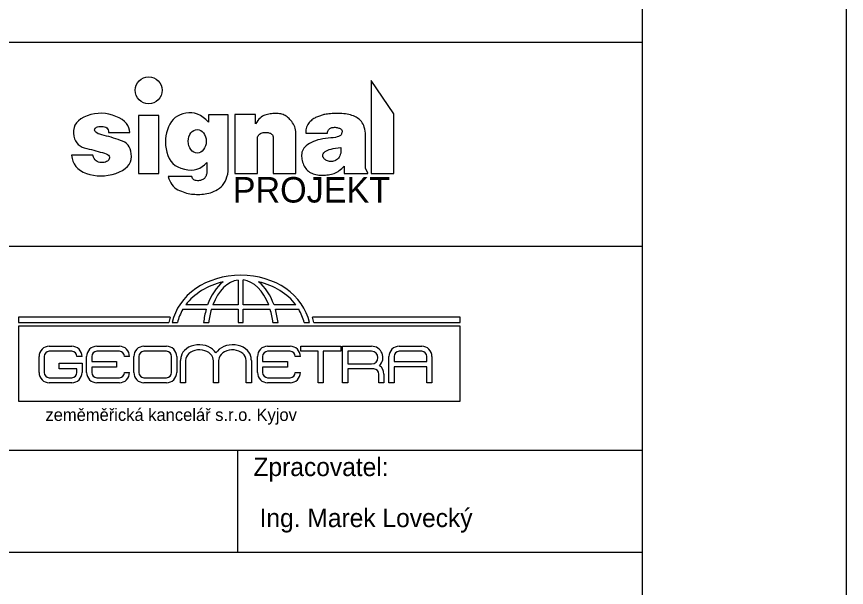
# Model space of a CAD drawing. Extents: x 1391 to 5528, y -6194 to 565.
# Drawn here: x 4054.2 to 4135.6, y -5727.5 to -5671.5 of the extents above; entities that cross this region are included whole.
import ezdxf

# ---------------------------------------------------------------- set-up
doc = ezdxf.new("R2010")
doc.units = 0
for name, color, linetype in [('Default', 7, 'Continuous'), ('Vrstva 1', 7, 'Continuous'), ('Vrstva 11', 7, 'Continuous'), ('Vrstva 17', 7, 'Continuous'), ('Vrstva 6', 7, 'Continuous')]:
    doc.layers.add(name, color=color, linetype=linetype)

msp = doc.modelspace()

# ---------------------------------------------------------------- linework, layer by layer
at = {"layer": 'Default'}
msp.add_lwpolyline([(3925.563, -5826.032), (4135.563, -5826.032), (4135.563, -5529.032), (3925.563, -5529.032)], close=True, dxfattribs=at)
at = {"layer": 'Vrstva 1'}
msp.add_lwpolyline([(3945.563, -5549.032), (4115.563, -5549.032), (4115.563, -5809.032), (3945.563, -5809.032)], close=True, dxfattribs=at)
at = {"layer": 'Vrstva 11'}
for points in [[(4091.228, -5686.911), (4091.228, -5681.071), (4088.988, -5677.791), (4088.988, -5686.911), (4091.228, -5686.911)], [(4062.499, -5687.146), (4062.861, -5687.13), (4063.228, -5687.082), (4063.599, -5687.003), (4063.975, -5686.893), (4064.329, -5686.756), (4064.637, -5686.6), (4064.898, -5686.424), (4065.112, -5686.228), (4065.28, -5686.012), (4065.4, -5685.776), (4065.474, -5685.521), (4065.5, -5685.245), (4065.49, -5684.971), (4065.451, -5684.722), (4065.385, -5684.498), (4065.291, -5684.299), (4065.17, -5684.124), (4065.021, -5683.974), (4064.844, -5683.849), (4064.639, -5683.748), (4064.42, -5683.662), (4064.198, -5683.58), (4063.973, -5683.503), (4063.747, -5683.43), (4063.518, -5683.361), (4063.287, -5683.297), (4063.054, -5683.237), (4062.818, -5683.182), (4062.596, -5683.127), (4062.405, -5683.068), (4062.244, -5683.005), (4062.114, -5682.938), (4062.014, -5682.867), (4061.945, -5682.791), (4061.906, -5682.712), (4061.897, -5682.629), (4061.914, -5682.55), (4061.95, -5682.481), (4062.006, -5682.423), (4062.082, -5682.376), (4062.178, -5682.339), (4062.294, -5682.314), (4062.429, -5682.299), (4062.585, -5682.296), (4062.74, -5682.306), (4062.875, -5682.335), (4062.99, -5682.383), (4063.085, -5682.448), (4063.16, -5682.532), (4063.214, -5682.635), (4063.249, -5682.755), (4063.263, -5682.894), (4065.342, -5682.894), (4065.323, -5682.652), (4065.261, -5682.422), (4065.156, -5682.205), (4065.008, -5682.001), (4064.817, -5681.809), (4064.583, -5681.631), (4064.307, -5681.464), (4063.987, -5681.311), (4063.645, -5681.182), (4063.3, -5681.087), (4062.952, -5681.027), (4062.602, -5681.002), (4062.249, -5681.012), (4061.894, -5681.057), (4061.535, -5681.137), (4061.174, -5681.252), (4060.836, -5681.394), (4060.547, -5681.557), (4060.306, -5681.74), (4060.114, -5681.944), (4059.971, -5682.168), (4059.876, -5682.413), (4059.83, -5682.679), (4059.832, -5682.964), (4059.872, -5683.246), (4059.938, -5683.498), (4060.03, -5683.72), (4060.148, -5683.913), (4060.293, -5684.076), (4060.464, -5684.21), (4060.661, -5684.315), (4060.885, -5684.389), (4061.12, -5684.449), (4061.351, -5684.509), (4061.578, -5684.568), (4061.802, -5684.627), (4062.023, -5684.686), (4062.239, -5684.744), (4062.452, -5684.802), (4062.662, -5684.86), (4062.854, -5684.92), (4063.016, -5684.984), (4063.146, -5685.053), (4063.246, -5685.126), (4063.314, -5685.204), (4063.352, -5685.287), (4063.359, -5685.374), (4063.335, -5685.465), (4063.289, -5685.553), (4063.228, -5685.629), (4063.152, -5685.694), (4063.062, -5685.747), (4062.958, -5685.789), (4062.84, -5685.819), (4062.707, -5685.837), (4062.559, -5685.844), (4062.411, -5685.833), (4062.275, -5685.8), (4062.152, -5685.744), (4062.04, -5685.666), (4061.942, -5685.565), (4061.855, -5685.441), (4061.781, -5685.294), (4061.72, -5685.126), (4059.639, -5685.126), (4059.683, -5685.433), (4059.767, -5685.715), (4059.89, -5685.973), (4060.052, -5686.206), (4060.254, -5686.416), (4060.496, -5686.601), (4060.778, -5686.762), (4061.099, -5686.899), (4061.442, -5687.008), (4061.79, -5687.085), (4062.142, -5687.131), (4062.499, -5687.146)], [(4068.188, -5686.911), (4068.188, -5681.231), (4066.188, -5681.231), (4066.188, -5686.911), (4068.188, -5686.911)], [(4072.047, -5688.954), (4072.216, -5688.95), (4072.386, -5688.941), (4072.558, -5688.928), (4072.731, -5688.91), (4072.905, -5688.883), (4073.079, -5688.844), (4073.253, -5688.793), (4073.426, -5688.729), (4073.6, -5688.654), (4073.772, -5688.566), (4073.945, -5688.466), (4074.117, -5688.354), (4074.282, -5688.225), (4074.43, -5688.072), (4074.563, -5687.896), (4074.679, -5687.698), (4074.78, -5687.476), (4074.865, -5687.231), (4074.934, -5686.963), (4074.988, -5686.671), (4074.988, -5681.151), (4073.068, -5681.151), (4073.068, -5681.871), (4072.802, -5681.617), (4072.531, -5681.404), (4072.257, -5681.232), (4071.978, -5681.101), (4071.695, -5681.011), (4071.407, -5680.962), (4071.116, -5680.954), (4070.82, -5680.988), (4070.533, -5681.056), (4070.267, -5681.153), (4070.024, -5681.278), (4069.802, -5681.432), (4069.602, -5681.614), (4069.423, -5681.825), (4069.267, -5682.065), (4069.132, -5682.333), (4069.022, -5682.618), (4068.937, -5682.911), (4068.878, -5683.212), (4068.845, -5683.519), (4068.838, -5683.834), (4068.857, -5684.155), (4068.901, -5684.484), (4068.972, -5684.82), (4069.072, -5685.144), (4069.205, -5685.434), (4069.37, -5685.692), (4069.568, -5685.918), (4069.799, -5686.11), (4070.062, -5686.27), (4070.358, -5686.398), (4070.687, -5686.493), (4071.023, -5686.551), (4071.342, -5686.568), (4071.643, -5686.545), (4071.926, -5686.481), (4072.191, -5686.376), (4072.438, -5686.23), (4072.668, -5686.044), (4072.88, -5685.817), (4072.88, -5686.894), (4072.861, -5686.982), (4072.838, -5687.063), (4072.81, -5687.139), (4072.778, -5687.209), (4072.742, -5687.274), (4072.701, -5687.333), (4072.655, -5687.386), (4072.605, -5687.433), (4072.55, -5687.474), (4072.487, -5687.511), (4072.417, -5687.542), (4072.34, -5687.567), (4072.256, -5687.587), (4072.165, -5687.602), (4072.067, -5687.612), (4071.962, -5687.616), (4071.858, -5687.61), (4071.765, -5687.592), (4071.682, -5687.56), (4071.609, -5687.515), (4071.546, -5687.456), (4071.493, -5687.385), (4071.451, -5687.3), (4071.418, -5687.202), (4069.111, -5687.202), (4069.18, -5687.429), (4069.264, -5687.638), (4069.361, -5687.828), (4069.472, -5688), (4069.596, -5688.152), (4069.735, -5688.286), (4069.887, -5688.401), (4070.053, -5688.498), (4070.225, -5688.581), (4070.396, -5688.655), (4070.565, -5688.72), (4070.733, -5688.777), (4070.899, -5688.826), (4071.064, -5688.866), (4071.227, -5688.897), (4071.389, -5688.919), (4071.551, -5688.935), (4071.715, -5688.946), (4071.88, -5688.952), (4072.047, -5688.954)], [(4081.628, -5686.911), (4081.628, -5683.111), (4081.624, -5682.942), (4081.61, -5682.778), (4081.586, -5682.622), (4081.55, -5682.472), (4081.504, -5682.328), (4081.447, -5682.191), (4081.379, -5682.061), (4081.301, -5681.937), (4081.216, -5681.821), (4081.129, -5681.713), (4081.04, -5681.613), (4080.949, -5681.521), (4080.856, -5681.438), (4080.761, -5681.363), (4080.664, -5681.296), (4080.565, -5681.237), (4080.462, -5681.185), (4080.356, -5681.141), (4080.245, -5681.104), (4080.13, -5681.073), (4080.011, -5681.05), (4079.887, -5681.033), (4079.759, -5681.023), (4079.627, -5681.021), (4079.493, -5681.024), (4079.361, -5681.032), (4079.229, -5681.045), (4079.099, -5681.063), (4078.97, -5681.086), (4078.842, -5681.114), (4078.716, -5681.147), (4078.59, -5681.184), (4078.467, -5681.233), (4078.345, -5681.297), (4078.226, -5681.379), (4078.11, -5681.476), (4077.996, -5681.59), (4077.884, -5681.721), (4077.775, -5681.868), (4077.668, -5682.031), (4077.668, -5681.111), (4075.628, -5681.111), (4075.628, -5686.911), (4077.868, -5686.911), (4077.868, -5683.351), (4077.902, -5683.26), (4077.946, -5683.179), (4078.001, -5683.108), (4078.065, -5683.047), (4078.139, -5682.996), (4078.223, -5682.955), (4078.317, -5682.924), (4078.421, -5682.903), (4078.527, -5682.89), (4078.628, -5682.883), (4078.723, -5682.883), (4078.814, -5682.888), (4078.899, -5682.899), (4078.978, -5682.917), (4079.053, -5682.941), (4079.122, -5682.97), (4079.184, -5683.005), (4079.238, -5683.044), (4079.284, -5683.086), (4079.321, -5683.131), (4079.35, -5683.181), (4079.371, -5683.234), (4079.383, -5683.291), (4079.388, -5683.351), (4079.388, -5686.911), (4081.628, -5686.911)], [(4084.19, -5687.075), (4084.352, -5687.073), (4084.51, -5687.064), (4084.663, -5687.05), (4084.812, -5687.03), (4084.956, -5687.004), (4085.097, -5686.972), (4085.233, -5686.935), (4085.364, -5686.892), (4085.493, -5686.841), (4085.62, -5686.779), (4085.746, -5686.707), (4085.869, -5686.625), (4085.991, -5686.532), (4086.112, -5686.429), (4086.23, -5686.315), (4086.348, -5686.191), (4086.348, -5686.911), (4088.668, -5686.911), (4088.668, -5686.831), (4088.428, -5686.431), (4088.428, -5682.951), (4088.401, -5682.747), (4088.365, -5682.557), (4088.32, -5682.381), (4088.265, -5682.22), (4088.201, -5682.073), (4088.127, -5681.941), (4088.043, -5681.823), (4087.95, -5681.719), (4087.849, -5681.627), (4087.742, -5681.541), (4087.628, -5681.462), (4087.508, -5681.39), (4087.382, -5681.325), (4087.25, -5681.267), (4087.111, -5681.216), (4086.966, -5681.172), (4086.814, -5681.134), (4086.655, -5681.102), (4086.489, -5681.075), (4086.315, -5681.055), (4086.135, -5681.04), (4085.947, -5681.03), (4085.751, -5681.027), (4085.549, -5681.029), (4085.35, -5681.035), (4085.166, -5681.043), (4084.997, -5681.054), (4084.843, -5681.066), (4084.703, -5681.081), (4084.578, -5681.098), (4084.467, -5681.118), (4084.372, -5681.14), (4084.283, -5681.163), (4084.194, -5681.189), (4084.104, -5681.217), (4084.013, -5681.246), (4083.921, -5681.278), (4083.829, -5681.311), (4083.737, -5681.346), (4083.643, -5681.384), (4083.55, -5681.425), (4083.458, -5681.474), (4083.366, -5681.529), (4083.276, -5681.592), (4083.187, -5681.661), (4083.099, -5681.736), (4083.012, -5681.819), (4082.926, -5681.909), (4082.845, -5682.006), (4082.776, -5682.113), (4082.718, -5682.229), (4082.67, -5682.355), (4082.633, -5682.49), (4082.607, -5682.634), (4082.592, -5682.788), (4082.588, -5682.951), (4084.708, -5682.951), (4084.723, -5682.855), (4084.747, -5682.768), (4084.78, -5682.69), (4084.821, -5682.621), (4084.872, -5682.561), (4084.93, -5682.511), (4084.998, -5682.469), (4085.073, -5682.437), (4085.154, -5682.413), (4085.235, -5682.395), (4085.317, -5682.384), (4085.399, -5682.379), (4085.481, -5682.381), (4085.565, -5682.389), (4085.648, -5682.404), (4085.732, -5682.425), (4085.813, -5682.45), (4085.884, -5682.478), (4085.947, -5682.508), (4086, -5682.54), (4086.045, -5682.574), (4086.082, -5682.611), (4086.109, -5682.649), (4086.128, -5682.69), (4086.14, -5682.733), (4086.145, -5682.778), (4086.144, -5682.827), (4086.136, -5682.878), (4086.122, -5682.932), (4086.103, -5682.989), (4086.076, -5683.049), (4086.044, -5683.112), (4085.993, -5683.173), (4085.912, -5683.229), (4085.801, -5683.28), (4085.659, -5683.325), (4085.487, -5683.365), (4085.285, -5683.4), (4085.052, -5683.429), (4084.789, -5683.453), (4084.517, -5683.48), (4084.258, -5683.517), (4084.01, -5683.565), (4083.775, -5683.624), (4083.553, -5683.693), (4083.342, -5683.772), (4083.144, -5683.862), (4082.958, -5683.963), (4082.789, -5684.071), (4082.641, -5684.184), (4082.513, -5684.301), (4082.407, -5684.423), (4082.321, -5684.549), (4082.256, -5684.68), (4082.212, -5684.815), (4082.189, -5684.955), (4082.181, -5685.096), (4082.182, -5685.236), (4082.192, -5685.375), (4082.211, -5685.513), (4082.239, -5685.65), (4082.276, -5685.785), (4082.322, -5685.919), (4082.377, -5686.053), (4082.44, -5686.181), (4082.51, -5686.3), (4082.587, -5686.41), (4082.671, -5686.512), (4082.761, -5686.604), (4082.859, -5686.688), (4082.964, -5686.763), (4083.075, -5686.829), (4083.193, -5686.887), (4083.317, -5686.937), (4083.447, -5686.979), (4083.584, -5687.014), (4083.726, -5687.041), (4083.875, -5687.06), (4084.03, -5687.072), (4084.19, -5687.075)], [(4084.906, -5685.731), (4084.803, -5685.71), (4084.708, -5685.682), (4084.622, -5685.646), (4084.543, -5685.603), (4084.472, -5685.551), (4084.409, -5685.492), (4084.354, -5685.426), (4084.307, -5685.351), (4084.273, -5685.273), (4084.255, -5685.196), (4084.254, -5685.12), (4084.27, -5685.045), (4084.302, -5684.971), (4084.351, -5684.898), (4084.417, -5684.826), (4084.5, -5684.754), (4084.603, -5684.686), (4084.732, -5684.623), (4084.886, -5684.565), (4085.065, -5684.513), (4085.269, -5684.465), (4085.498, -5684.424), (4085.753, -5684.387), (4086.032, -5684.356), (4086.037, -5684.554), (4086.028, -5684.736), (4086.006, -5684.902), (4085.972, -5685.052), (4085.924, -5685.186), (4085.864, -5685.303), (4085.79, -5685.404), (4085.704, -5685.49), (4085.611, -5685.561), (4085.515, -5685.62), (4085.418, -5685.668), (4085.319, -5685.704), (4085.219, -5685.728), (4085.116, -5685.741), (4085.012, -5685.742), (4084.906, -5685.731)]]:
    msp.add_lwpolyline(points, dxfattribs=at)
msp.add_circle((4067.188, -5678.751), 1.32, dxfattribs=at)
msp.add_ellipse((4071.948, -5683.751), major_axis=(0, 1.16), ratio=0.758621, dxfattribs=at)
at = {"layer": 'Vrstva 17'}
for p, q in [((4075.958, -5697.345), (4075.958, -5699.791)), ((4076.465, -5699.791), (4076.465, -5697.343)), ((4072.965, -5699.791), (4070.82, -5699.791)), ((4075.958, -5699.791), (4073.482, -5699.791)), ((4078.96, -5699.791), (4076.465, -5699.791)), ((4081.622, -5699.791), (4079.477, -5699.791)), ((4070.545, -5700.202), (4072.832, -5700.202)), ((4073.342, -5700.202), (4075.958, -5700.202)), ((4075.958, -5700.202), (4075.958, -5701.523)), ((4076.465, -5701.523), (4076.465, -5700.202)), ((4076.465, -5700.202), (4079.099, -5700.202)), ((4079.609, -5700.202), (4081.897, -5700.202)), ((4069.314, -5700.991), (4054.433, -5700.991)), ((4054.433, -5700.991), (4054.433, -5701.523)), ((4054.433, -5701.523), (4069.176, -5701.523)), ((4069.502, -5701.523), (4070.019, -5701.523)), ((4072.575, -5701.523), (4073.075, -5701.523)), ((4075.958, -5701.523), (4076.465, -5701.523)), ((4079.366, -5701.523), (4079.866, -5701.523)), ((4082.423, -5701.523), (4082.94, -5701.523)), ((4097.712, -5700.991), (4083.233, -5700.991)), ((4083.371, -5701.523), (4097.712, -5701.523)), ((4097.712, -5701.523), (4097.712, -5700.991)), ((4097.71, -5701.867), (4054.427, -5701.867)), ((4054.427, -5701.867), (4054.427, -5709.205)), ((4097.71, -5709.205), (4097.71, -5701.867)), ((4057.452, -5703.833), (4059.663, -5703.833)), ((4062.108, -5703.833), (4064.319, -5703.833)), ((4066.732, -5703.833), (4068.943, -5703.833)), ((4078.851, -5703.833), (4081.061, -5703.833)), ((4086.188, -5703.833), (4089.032, -5703.833)), ((4091.736, -5703.833), (4093.947, -5703.833)), ((4056.454, -5706.417), (4056.454, -5704.831)), ((4056.953, -5704.831), (4056.953, -5706.417)), ((4059.663, -5704.332), (4057.452, -5704.332)), ((4060.66, -5704.831), (4060.162, -5704.831)), ((4061.11, -5706.417), (4061.11, -5704.831)), ((4061.609, -5704.831), (4061.609, -5705.341)), ((4064.319, -5704.332), (4062.108, -5704.332)), ((4065.317, -5704.831), (4064.818, -5704.831)), ((4065.734, -5706.417), (4065.734, -5704.831)), ((4066.233, -5704.831), (4066.233, -5706.417)), ((4068.943, -5704.332), (4066.732, -5704.332)), ((4069.442, -5706.417), (4069.442, -5704.831)), ((4069.941, -5704.831), (4069.941, -5706.417)), ((4077.853, -5706.417), (4077.853, -5704.831)), ((4078.352, -5704.831), (4078.352, -5705.341)), ((4081.061, -5704.332), (4078.851, -5704.332)), ((4082.059, -5704.831), (4081.56, -5704.831)), ((4083.794, -5707.415), (4083.794, -5704.32)), ((4084.297, -5704.32), (4084.297, -5707.415)), ((4089.032, -5704.322), (4086.692, -5704.322)), ((4086.692, -5704.322), (4086.692, -5705.572)), ((4090.738, -5707.415), (4090.738, -5704.831)), ((4091.237, -5704.831), (4091.237, -5705.339)), ((4093.947, -5704.332), (4091.736, -5704.332)), ((4094.446, -5705.339), (4094.446, -5704.831)), ((4094.945, -5704.831), (4094.945, -5707.415)), ((4058.427, -5706.039), (4058.427, -5705.494)), ((4058.427, -5705.494), (4060.66, -5705.494)), ((4060.66, -5705.494), (4060.66, -5706.417)), ((4061.609, -5705.341), (4064.052, -5705.341)), ((4064.052, -5705.341), (4064.052, -5705.886)), ((4070.313, -5707.415), (4070.313, -5705.23)), ((4070.814, -5705.23), (4070.814, -5707.415)), ((4073.533, -5707.415), (4073.533, -5705.23)), ((4074.033, -5705.23), (4074.033, -5707.415)), ((4076.752, -5707.415), (4076.752, -5705.23)), ((4077.253, -5705.23), (4077.253, -5707.415)), ((4078.352, -5705.341), (4080.795, -5705.341)), ((4080.795, -5705.341), (4080.795, -5705.886)), ((4086.692, -5705.572), (4089.032, -5705.572)), ((4091.237, -5705.339), (4094.446, -5705.339)), ((4060.162, -5706.039), (4058.427, -5706.039)), ((4060.162, -5706.417), (4060.162, -5706.039)), ((4064.052, -5705.886), (4061.609, -5705.886)), ((4061.609, -5705.886), (4061.609, -5706.417)), ((4064.818, -5706.417), (4065.317, -5706.417)), ((4080.795, -5705.886), (4078.352, -5705.886)), ((4078.352, -5705.886), (4078.352, -5706.417)), ((4081.56, -5706.417), (4082.059, -5706.417)), ((4089.032, -5706.06), (4086.692, -5706.06)), ((4089.247, -5706.064), (4089.032, -5706.06)), ((4089.746, -5707.415), (4089.746, -5706.563)), ((4090.244, -5706.563), (4090.244, -5707.415)), ((4094.446, -5705.843), (4091.237, -5705.843)), ((4091.237, -5705.843), (4091.237, -5707.415)), ((4094.446, -5707.415), (4094.446, -5705.843)), ((4057.452, -5706.916), (4059.663, -5706.916)), ((4062.108, -5706.916), (4064.319, -5706.916)), ((4066.732, -5706.916), (4068.943, -5706.916)), ((4078.851, -5706.916), (4081.061, -5706.916)), ((4059.663, -5707.415), (4057.452, -5707.415)), ((4064.319, -5707.415), (4062.108, -5707.415)), ((4068.943, -5707.415), (4066.732, -5707.415)), ((4070.814, -5707.415), (4070.313, -5707.415)), ((4074.033, -5707.415), (4073.533, -5707.415)), ((4077.253, -5707.415), (4076.752, -5707.415)), ((4081.061, -5707.415), (4078.851, -5707.415)), ((4084.297, -5707.415), (4083.794, -5707.415)), ((4090.244, -5707.415), (4089.746, -5707.415)), ((4091.237, -5707.415), (4090.738, -5707.415)), ((4094.945, -5707.415), (4094.446, -5707.415)), ((4054.427, -5709.205), (4097.71, -5709.205))]:
    msp.add_line(p, q, dxfattribs=at)
for points in [[(4083.794, -5704.32), (4082.096, -5704.32), (4082.096, -5703.833), (4086.009, -5703.833)], [(4086.009, -5703.833), (4086.009, -5704.32), (4084.297, -5704.32)], [(4086.692, -5706.06), (4086.692, -5707.415), (4086.188, -5707.415), (4086.188, -5703.833)]]:
    msp.add_lwpolyline(points, dxfattribs=at)
for centre, radius, start, end in [((4057.452, -5704.831), 0.998, 90, 180), ((4059.663, -5704.831), 0.998, 360, 90), ((4062.108, -5704.831), 0.998, 90, 180), ((4064.319, -5704.831), 0.998, 360, 90), ((4066.732, -5704.831), 0.998, 90, 180), ((4068.943, -5704.831), 0.998, 360, 90), ((4078.851, -5704.831), 0.998, 90, 180), ((4081.061, -5704.831), 0.998, 360, 90), ((4089.032, -5704.947), 1.114, 314.45734, 90), ((4091.736, -5704.831), 0.998, 90, 180), ((4093.947, -5704.831), 0.998, 360, 90), ((4057.452, -5704.831), 0.499, 90, 180), ((4059.663, -5704.831), 0.499, 0, 90), ((4062.108, -5704.831), 0.499, 90, 180), ((4064.319, -5704.831), 0.499, 0, 90), ((4066.732, -5704.831), 0.499, 90, 180), ((4068.943, -5704.831), 0.499, 0, 90), ((4072.25, -5705.28), 1.938, 166.96576, 178.52091), ((4072.579, -5705.294), 0.957, 3.86486, 22.41569), ((4075.315, -5705.28), 1.938, 1.47909, 13.03424), ((4078.851, -5704.831), 0.499, 90, 180), ((4081.061, -5704.831), 0.499, 0, 90), ((4089.032, -5704.947), 0.625, 270, 90), ((4091.736, -5704.831), 0.499, 90, 180), ((4093.947, -5704.831), 0.499, 0, 90), ((4075.266, -5705.352), 1.238, 162.61388, 174.3506), ((4089.247, -5706.563), 0.998, 360, 55.44734), ((4057.452, -5706.417), 0.998, 180, 270), ((4057.452, -5706.417), 0.499, 180, 270), ((4059.663, -5706.417), 0.998, 270, 0), ((4059.663, -5706.417), 0.499, 270, 0), ((4062.108, -5706.417), 0.998, 180, 270), ((4062.108, -5706.417), 0.499, 180, 270), ((4064.319, -5706.417), 0.998, 270, 0), ((4064.319, -5706.417), 0.499, 270, 0), ((4066.732, -5706.417), 0.998, 180, 270), ((4066.732, -5706.417), 0.499, 180, 270), ((4068.943, -5706.417), 0.998, 270, 0), ((4068.943, -5706.417), 0.499, 270, 0), ((4078.851, -5706.417), 0.998, 180, 270), ((4078.851, -5706.417), 0.499, 180, 270), ((4081.061, -5706.417), 0.998, 270, 0), ((4081.061, -5706.417), 0.499, 270, 0), ((4089.247, -5706.563), 0.499, 0, 90)]:
    msp.add_arc(centre, radius, start, end, dxfattribs=at)
for centre, major_axis, ratio, start_param, end_param in [((4076.221, -5702.395), (-6.804, 0), 0.811768, 3.300239, 6.124539), ((4076.221, -5702.395), (-6.296, 0), 0.804826, 4.992897, 5.743383), ((4076.221, -5702.395), (0, 5.524), 0.668443, 0.491666, 1.079789), ((4076.221, -5702.395), (0, 5.067), 0.630136, 0.08224, 1.030995), ((4076.221, -5702.395), (0, 5.067), 0.630136, 5.252191, 6.206521), ((4076.221, -5702.395), (0, 5.524), 0.668443, 5.203397, 5.79152), ((4076.221, -5702.395), (-6.296, 0), 0.804826, 3.681394, 4.431881), ((4076.221, -5702.395), (-6.296, 0), 0.804826, 5.835664, 6.110118), ((4076.221, -5702.395), (0, 5.524), 0.668443, 1.16256, 1.41215), ((4076.221, -5702.395), (0, 5.067), 0.630136, 1.123275, 1.397729), ((4076.221, -5702.395), (0, 5.067), 0.630136, 4.885456, 5.159911), ((4076.221, -5702.395), (0, 5.524), 0.668443, 4.871035, 5.120625), ((4076.221, -5702.395), (-6.296, 0), 0.804826, 3.31466, 3.589114), ((4075.895, -5702.395), (-6.804, 0), 0.811768, 6.026233, 6.124539), ((4076.653, -5702.395), (-6.804, 0), 0.811768, 3.300239, 3.398545), ((4072.142, -5705.074), (1.805, 0), 0.766187, 0.429647, 2.97338), ((4075.424, -5705.074), (-1.805, 0), 0.766187, 3.309805, 5.853538), ((4072.167, -5705.23), (1.354, 0), 0.766187, 0.29376, 3.141593), ((4075.398, -5705.23), (-1.354, 0), 0.766187, 3.141593, 6.041607)]:
    msp.add_ellipse(centre, major_axis=major_axis, ratio=ratio, start_param=start_param, end_param=end_param, dxfattribs=at)
at = {"layer": 'Vrstva 6'}
for p, q in [((3945.563, -5694.032), (4115.563, -5694.032)), ((3945.563, -5714.032), (4115.563, -5714.032)), ((4075.913, -5724.032), (4075.913, -5714.032))]:
    msp.add_line(p, q, dxfattribs=at)
msp.add_lwpolyline([(3945.563, -5674.032), (4115.563, -5674.032), (4115.563, -5724.032), (3945.563, -5724.032)], close=True, dxfattribs=at)

# ---------------------------------------------------------------- texts
at = {"layer": 'Vrstva 11'}
msp.add_text('PROJEKT', height=2.5, dxfattribs=at).set_placement((4075.428, -5689.754))
at = {"layer": 'Vrstva 17'}
msp.add_text('zeměměřická kancelář s.r.o. Kyjov', height=1.20984, dxfattribs=at).set_placement((4057.079, -5711.154))
at = {"layer": 'Vrstva 6'}
for s, p in [('Zpracovatel:', (4077.459, -5716.559)), ('Ing. Marek Lovecký', (4078.06, -5721.559))]:
    msp.add_text(s, height=1.8, dxfattribs=at).set_placement(p)

doc.saveas('drawing.dxf')
